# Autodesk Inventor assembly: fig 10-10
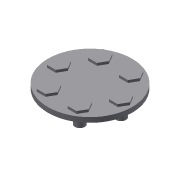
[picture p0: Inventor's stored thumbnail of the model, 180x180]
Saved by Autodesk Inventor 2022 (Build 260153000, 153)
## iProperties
Created: 2008-05
Part Number: fig 10-10
Document SubType Name: Assembly
Designer: CADCIM
Author: CADCIM
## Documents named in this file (3)
- D:\PROJECTS_2021\Resources\Part Files\c10_Inv_2021_prt\fig 10-10.iam
- D:\PROJECTS_2021\Resources\Part Files\c10_Inv_2021_prt\Part4.ipt
- D:\PROJECTS_2021\Resources\Part Files\c10_Inv_2021_prt\Part5.ipt
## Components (7 placed, 2 different names)
1. Part4:1
2. Part5:1
3. Part5:2
4. Part5:3
5. Part5:4
6. Part5:5
7. Part5:6
